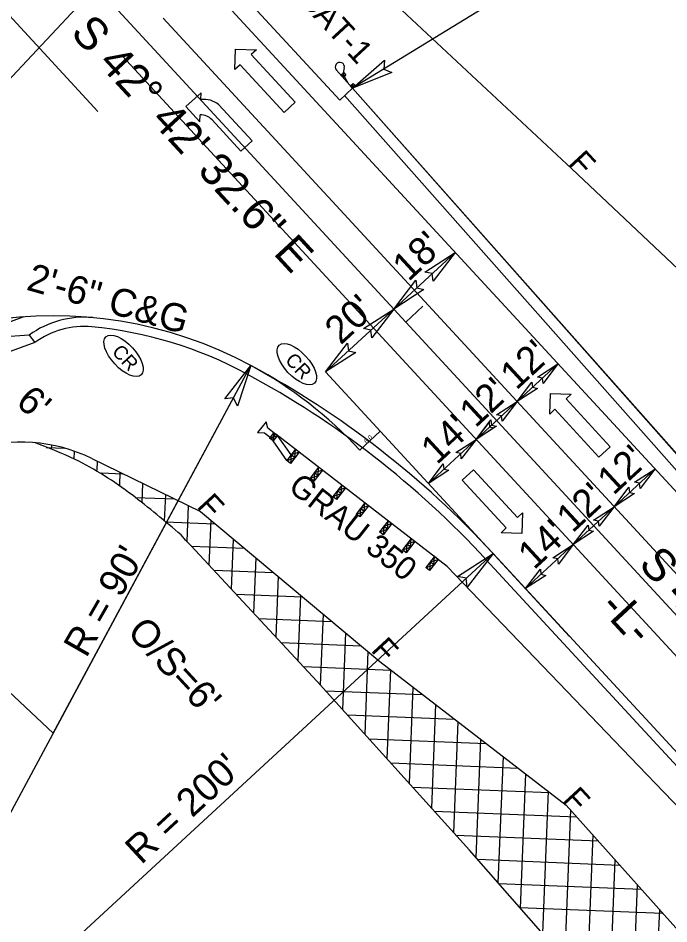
# Model space of a CAD drawing. Extents: x 1702862 to 1704514, y 793768 to 796215.
# Drawn here: x 1703316.6 to 1703456.9, y 795023.9 to 795219.2 of the extents above; entities that cross this region are included whole.
import ezdxf

# ---------------------------------------------------------------- set-up
doc = ezdxf.new("R2010")
doc.units = 0
for name, color, linetype in [('Default', 7, 'Continuous'), ('Prop Conc 2ft 6in Curb and Gutter', 7, 'Continuous'), ('Prop Conc Shoulder Berm Gutter', 7, 'Continuous'), ('Prop Dimension', 7, 'Continuous'), ('Prop Dimension Text', 7, 'Continuous'), ('Prop EOT', 7, 'Continuous'), ('Prop Guardrail', 7, 'Continuous'), ('Prop Guardrail Anchor Unit CELL', 7, 'Continuous'), ('Prop Horizontal Alignment', 7, 'Continuous'), ('Prop Horizontal Alignment Direction Label', 7, 'Continuous'), ('Prop Horizontal Alignment Tick Small', 7, 'Continuous'), ('Prop Lane Arrow CELL', 7, 'Continuous'), ('Prop Lane Lines', 7, 'Continuous'), ('Prop Leader Line Medium', 7, 'Continuous'), ('Prop Paved Shoulder', 7, 'Continuous'), ('Prop Rem of Exist Asph Pvmt', 7, 'Continuous'), ('Prop SS Fill Line', 7, 'Continuous'), ('Prop SS Misc', 7, 'Continuous'), ('Prop SS Transition Line', 7, 'Continuous'), ('Prop Structure Anchor Unit CELL', 7, 'Continuous'), ('Prop Terminator CELL', 7, 'Continuous'), ('Prop WCR CELL', 7, 'Continuous')]:
    doc.layers.add(name, color=color, linetype=linetype)

msp = doc.modelspace()

# ---------------------------------------------------------------- linework, layer by layer
at = {"layer": 'Default'}
msp.add_line((1703382.89, 795142.89), (1703435.5, 795085.89), dxfattribs=at)
at = {"layer": 'Prop Conc 2ft 6in Curb and Gutter'}
msp.add_line((1703417.51, 795102.43), (1703469.08, 795046.57), dxfattribs=at)
for centre, radius, start, end in [((1703330.77, 795134.69), 18, 84.5561, 126.0894), ((1703324.13, 795065.01), 88, 61.7203, 84.5561), ((1703272.02, 794968.13), 198, 42.7091, 61.7203)]:
    msp.add_arc(centre, radius, start, end, dxfattribs=at)
at = {"layer": 'Prop Conc Shoulder Berm Gutter'}
msp.add_line((1703388.7, 795204.04), (1703509.44, 795067.71), dxfattribs=at)
at = {"layer": 'Prop Dimension'}
for p, q in [((1703397.58, 795156.45), (1703410.81, 795168.66)), ((1703382.89, 795142.89), (1703397.58, 795156.45)), ((1703317.84, 795154.78), (1703304.2, 795149.85)), ((1703320.17, 795149.24), (1703306.25, 795144.2)), ((1703272.02, 794968.13), (1703366.77, 795144.26)), ((1703324.13, 795065.01), (1703366.77, 795144.26)), ((1703424.16, 795136.51), (1703432.98, 795144.65)), ((1703415.34, 795128.37), (1703424.16, 795136.51)), ((1703390.26, 795126.05), (1703394.67, 795130.12)), ((1703405.06, 795118.87), (1703415.34, 795128.37)), ((1703324.13, 795065.01), (1703258.57, 795126.66)), ((1703445.09, 795113.83), (1703453.91, 795121.97)), ((1703436.27, 795105.69), (1703445.09, 795113.83)), ((1703425.99, 795096.2), (1703436.27, 795105.69)), ((1703272.02, 794968.13), (1703418.98, 795103.79))]:
    msp.add_line(p, q, dxfattribs=at)
for start, end in [(136.7565, 136.7565), (42.7091, 61.7203)]:
    msp.add_arc((1703324.13, 795065.01), 90, start, end, dxfattribs=at)
at = {"layer": 'Prop EOT'}
for p, q in [((1703259.9, 795332.15), (1703737.14, 794815.13)), ((1703318.99, 795150.85), (1703320.17, 795149.24)), ((1703418.98, 795103.79), (1703636.58, 794868.05))]:
    msp.add_line(p, q, dxfattribs=at)
for centre, radius, start, end in [((1703324.13, 795065.01), 90, 61.7203, 136.7565), ((1703330.77, 795134.69), 20, 84.5561, 126.0894), ((1703272.02, 794968.13), 200, 42.7091, 61.7203)]:
    msp.add_arc(centre, radius, start, end, dxfattribs=at)
at = {"layer": 'Prop Guardrail'}
for p, q in [((1703513.1, 795063.75), (1703388.7, 795204.04)), ((1703409.13, 795100.95), (1703450.36, 795057.99)), ((1703450.36, 795057.99), (1703467.69, 795039.96))]:
    msp.add_line(p, q, dxfattribs=at)
at = {"layer": 'Prop Guardrail Anchor Unit CELL'}
for p, q in [((1703386.35, 795206.69), (1703385.21, 795207.98)), ((1703386.92, 795208.43), (1703386.7, 795207.36)), ((1703386.17, 795206.89), (1703386.78, 795207.43)), ((1703386.17, 795206.89), (1703387.24, 795206.9)), ((1703386.64, 795206.37), (1703386.17, 795206.89)), ((1703386.26, 795206.79), (1703386.35, 795206.69)), ((1703388.7, 795204.04), (1703386.35, 795206.69)), ((1703386.64, 795206.37), (1703386.78, 795207.43)), ((1703387.24, 795206.9), (1703386.64, 795206.37)), ((1703386.71, 795206.9), (1703387.67, 795205.21)), ((1703386.78, 795207.43), (1703387.24, 795206.9)), ((1703388.24, 795204.56), (1703388.84, 795205.1)), ((1703388.24, 795204.56), (1703389.3, 795204.58)), ((1703388.7, 795204.04), (1703388.24, 795204.56)), ((1703388.7, 795204.04), (1703388.84, 795205.1)), ((1703389.3, 795204.58), (1703388.7, 795204.04)), ((1703388.84, 795205.1), (1703389.3, 795204.58)), ((1703370.07, 795132.16), (1703368.23, 795129.87)), ((1703370.45, 795130.76), (1703370.07, 795132.16)), ((1703368.23, 795129.87), (1703369.69, 795129.8)), ((1703369.69, 795129.8), (1703371.29, 795128.52)), ((1703372.05, 795129.48), (1703370.45, 795130.76)), ((1703371.72, 795129.82), (1703370.81, 795128.63)), ((1703371.72, 795129.82), (1703371.6, 795128.02)), ((1703370.81, 795128.63), (1703372.52, 795129.21)), ((1703371.6, 795128.02), (1703370.81, 795128.63)), ((1703371.6, 795128.02), (1703371.2, 795128.33)), ((1703371.29, 795128.52), (1703371.67, 795129)), ((1703372.52, 795129.21), (1703371.6, 795128.02)), ((1703374.52, 795123.79), (1703371.6, 795128.02)), ((1703371.67, 795129), (1703372.05, 795129.48)), ((1703409.13, 795100.95), (1703372.12, 795129.52)), ((1703375.46, 795125), (1703372.52, 795129.21)), ((1703376.4, 795126.22), (1703374.52, 795123.79)), ((1703376.25, 795124.39), (1703376.4, 795126.22)), ((1703374.52, 795123.79), (1703376.25, 795124.39)), ((1703377.19, 795125.6), (1703375.32, 795123.18)), ((1703375.46, 795125), (1703375.32, 795123.18)), ((1703377.19, 795125.6), (1703375.46, 795125)), ((1703376.25, 795124.39), (1703375.46, 795125)), ((1703375.32, 795123.18), (1703374.52, 795123.79)), ((1703381.38, 795122.37), (1703379.55, 795119.99)), ((1703381.26, 795120.57), (1703381.38, 795122.37)), ((1703379.55, 795119.99), (1703381.26, 795120.57)), ((1703380.34, 795119.38), (1703379.55, 795119.99)), ((1703382.18, 795121.75), (1703380.34, 795119.38)), ((1703380.47, 795121.18), (1703380.34, 795119.38)), ((1703382.18, 795121.75), (1703380.47, 795121.18)), ((1703381.26, 795120.57), (1703380.47, 795121.18)), ((1703386.37, 795118.52), (1703384.46, 795116.03)), ((1703386.21, 795116.66), (1703386.37, 795118.52)), ((1703384.46, 795116.03), (1703386.21, 795116.66)), ((1703385.25, 795115.42), (1703384.46, 795116.03)), ((1703387.16, 795117.9), (1703385.25, 795115.42)), ((1703385.41, 795117.27), (1703385.25, 795115.42)), ((1703387.16, 795117.9), (1703385.41, 795117.27)), ((1703386.21, 795116.66), (1703385.41, 795117.27)), ((1703391.36, 795114.67), (1703389.51, 795112.26)), ((1703391.22, 795112.85), (1703391.36, 795114.67)), ((1703392.15, 795114.05), (1703391.36, 795114.67)), ((1703389.51, 795112.26), (1703391.22, 795112.85)), ((1703390.3, 795111.65), (1703389.51, 795112.26)), ((1703392.15, 795114.05), (1703390.3, 795111.65)), ((1703390.43, 795113.46), (1703390.3, 795111.65)), ((1703392.15, 795114.05), (1703390.43, 795113.46)), ((1703391.22, 795112.85), (1703390.43, 795113.46)), ((1703396.35, 795110.82), (1703394.49, 795108.4)), ((1703397.14, 795110.2), (1703395.28, 795107.79)), ((1703397.14, 795110.2), (1703395.42, 795109.61)), ((1703396.21, 795109), (1703396.35, 795110.82)), ((1703394.49, 795108.4), (1703396.21, 795109)), ((1703395.28, 795107.79), (1703394.49, 795108.4)), ((1703395.42, 795109.61), (1703395.28, 795107.79)), ((1703396.21, 795109), (1703395.42, 795109.61)), ((1703401.34, 795106.97), (1703399.47, 795104.55)), ((1703402.13, 795106.35), (1703400.26, 795103.94)), ((1703402.13, 795106.35), (1703400.4, 795105.76)), ((1703401.2, 795105.15), (1703401.34, 795106.97)), ((1703399.47, 795104.55), (1703401.2, 795105.15)), ((1703400.26, 795103.94), (1703399.47, 795104.55)), ((1703400.4, 795105.76), (1703400.26, 795103.94)), ((1703401.2, 795105.15), (1703400.4, 795105.76)), ((1703406.33, 795103.11), (1703404.49, 795100.74)), ((1703407.12, 795102.5), (1703405.28, 795100.13)), ((1703406.33, 795103.11), (1703405.41, 795101.93)), ((1703405.41, 795101.93), (1703407.12, 795102.5)), ((1703406.2, 795101.32), (1703406.33, 795103.11)), ((1703407.12, 795102.5), (1703406.33, 795103.11)), ((1703404.49, 795100.74), (1703406.2, 795101.32)), ((1703405.28, 795100.13), (1703404.49, 795100.74)), ((1703405.41, 795101.93), (1703405.28, 795100.13)), ((1703406.2, 795101.32), (1703405.41, 795101.93))]:
    msp.add_line(p, q, dxfattribs=at)
msp.add_ellipse((1703385.95, 795208.64), major_axis=(-0.743, -0.659), ratio=0.995379, start_param=2.210226, end_param=6.283185, dxfattribs=at)
at = {"layer": 'Prop Horizontal Alignment'}
for p, q in [((1703246.67, 795319.94), (1703723.92, 794802.92)), ((1703333.42, 795225.96), (1703157.53, 795038.5))]:
    msp.add_line(p, q, dxfattribs=at)
at = {"layer": 'Prop Horizontal Alignment Tick Small'}
msp.add_line((1703400.17, 795153.65), (1703403.84, 795157.05), dxfattribs=at)
at = {"layer": 'Prop Lane Arrow CELL'}
for p, q in [((1703363.33, 795208.07), (1703363.47, 795212.49)), ((1703363.47, 795212.49), (1703367.96, 795212.34)), ((1703367.96, 795212.34), (1703366.86, 795211.32)), ((1703366.86, 795211.32), (1703376.35, 795201.04)), ((1703364.43, 795209.09), (1703363.33, 795208.07)), ((1703373.93, 795198.8), (1703364.43, 795209.09)), ((1703356.04, 795203.09), (1703352.77, 795200.14)), ((1703355.98, 795201.61), (1703356.04, 795203.09)), ((1703352.77, 795200.14), (1703355.79, 795196.8)), ((1703367.02, 795192.75), (1703359.86, 795200.5)), ((1703376.35, 795201.04), (1703373.93, 795198.8)), ((1703355.79, 795196.8), (1703355.85, 795198.29)), ((1703358.39, 795197.23), (1703364.59, 795190.51)), ((1703364.59, 795190.51), (1703367.02, 795192.75)), ((1703431.21, 795133.82), (1703431.35, 795138.24)), ((1703431.35, 795138.24), (1703435.84, 795138.1)), ((1703435.84, 795138.1), (1703434.74, 795137.08)), ((1703434.74, 795137.08), (1703444.24, 795126.79)), ((1703432.31, 795134.84), (1703431.21, 795133.82)), ((1703441.81, 795124.55), (1703432.31, 795134.84)), ((1703444.24, 795126.79), (1703441.81, 795124.55)), ((1703412.35, 795119.55), (1703414.77, 795121.78)), ((1703414.77, 795121.78), (1703424.27, 795111.5)), ((1703421.85, 795109.26), (1703412.35, 795119.55)), ((1703424.27, 795111.5), (1703425.37, 795112.51)), ((1703425.37, 795112.51), (1703425.23, 795108.1)), ((1703420.74, 795108.24), (1703421.85, 795109.26)), ((1703425.23, 795108.1), (1703420.74, 795108.24))]:
    msp.add_line(p, q, dxfattribs=at)
for centre, radius, start, end in [((1703356.6, 795196.41), 5.25, 51.3851, 96.6968), ((1703355.99, 795195.03), 3.27, 42.7091, 92.3672)]:
    msp.add_arc(centre, radius, start, end, dxfattribs=at)
at = {"layer": 'Prop Lane Lines'}
for p, q in [((1703233.45, 795307.73), (1703333.8, 795199.01)), ((1703347.89, 795219.14), (1703550.56, 794999.58)), ((1703339.07, 795211), (1703542.22, 794990.92))]:
    msp.add_line(p, q, dxfattribs=at)
at = {"layer": 'Prop Leader Line Medium'}
msp.add_line((1703492.5, 795267.75), (1703388.7, 795204.04), dxfattribs=at)
at = {"layer": 'Prop Paved Shoulder'}
for p, q in [((1703262.84, 795334.86), (1703385.95, 795201.5)), ((1703385.95, 795201.5), (1703388.7, 795204.04)), ((1703386.98, 795202.46), (1703507.31, 795066.6))]:
    msp.add_line(p, q, dxfattribs=at)
msp.add_arc((1703324.13, 795065.01), 86, 93.4265, 136.7565, dxfattribs=at)
at = {"layer": 'Prop Rem of Exist Asph Pvmt'}
for p, q in [((1703322.61, 795126.63), (1703326.65, 795126.47)), ((1703323.75, 795127.16), (1703323.71, 795126.17)), ((1703328.7, 795125.82), (1703328.63, 795124.13)), ((1703333.62, 795123.68), (1703333.54, 795121.71)), ((1703334.48, 795121.15), (1703339.17, 795120.96)), ((1703338.53, 795121.28), (1703338.41, 795118.51)), ((1703343.43, 795118.88), (1703343.27, 795114.67)), ((1703348.34, 795116.47), (1703348.11, 795110.71)), ((1703341.81, 795115.85), (1703350.31, 795115.51)), ((1703353.25, 795114.07), (1703352.94, 795106.37)), ((1703348.26, 795110.59), (1703359.03, 795110.16)), ((1703358.13, 795110.91), (1703357.74, 795101.25)), ((1703352.67, 795106.65), (1703351.72, 795107.76)), ((1703352.67, 795106.65), (1703353.81, 795105.47)), ((1703362.97, 795106.87), (1703362.54, 795096.09)), ((1703353.91, 795105.36), (1703365.32, 795104.9)), ((1703367.81, 795102.82), (1703367.34, 795090.94)), ((1703358.75, 795100.16), (1703371.62, 795099.65)), ((1703372.65, 795098.78), (1703372.13, 795085.79)), ((1703363.59, 795094.96), (1703377.91, 795094.39)), ((1703377.5, 795094.74), (1703376.93, 795080.64)), ((1703382.34, 795090.69), (1703381.73, 795075.46)), ((1703368.43, 795089.77), (1703384.21, 795089.13)), ((1703387.18, 795086.65), (1703386.52, 795070.15)), ((1703373.27, 795084.57), (1703390.5, 795083.88)), ((1703392.02, 795082.61), (1703391.31, 795064.84)), ((1703378.11, 795079.37), (1703396.99, 795078.62)), ((1703396.87, 795078.71), (1703396.1, 795059.53)), ((1703382.89, 795074.18), (1703403.84, 795073.34)), ((1703401.72, 795074.97), (1703400.89, 795054.22)), ((1703406.58, 795071.23), (1703405.69, 795048.91)), ((1703387.57, 795068.98), (1703410.69, 795068.06)), ((1703411.43, 795067.48), (1703410.48, 795043.6)), ((1703392.26, 795063.79), (1703417.54, 795062.78)), ((1703416.29, 795063.74), (1703415.27, 795038.25)), ((1703421.14, 795060), (1703420.05, 795032.8)), ((1703396.94, 795058.6), (1703424.39, 795057.5)), ((1703426, 795056.26), (1703424.84, 795027.34)), ((1703401.63, 795053.41), (1703431.24, 795052.23)), ((1703430.85, 795052.52), (1703429.63, 795021.89)), ((1703406.31, 795048.22), (1703437.01, 795046.99)), ((1703435.69, 795048.47), (1703434.41, 795016.44)), ((1703410.99, 795043.03), (1703441.64, 795041.8)), ((1703440.48, 795043.1), (1703439.2, 795010.99)), ((1703415.63, 795037.84), (1703446.27, 795036.61)), ((1703445.27, 795037.73), (1703443.98, 795005.35)), ((1703420.18, 795032.65), (1703450.9, 795031.42)), ((1703450.06, 795032.37), (1703448.82, 795001.4)), ((1703424.73, 795027.47), (1703455.53, 795026.23)), ((1703454.85, 795027), (1703453.93, 795004.05))]:
    msp.add_line(p, q, dxfattribs=at)
msp.add_lwpolyline([(1703446.88, 795000.39), (1703443.63, 795005.93), (1703413.93, 795039.78), (1703381.07, 795076.19), (1703353.81, 795105.47)], dxfattribs=at)
msp.add_spline([(1703351.72, 795107.76), (1703341.14, 795116.4), (1703328.87, 795124.03), (1703320.09, 795127.66)], degree=3, dxfattribs=at)
at = {"layer": 'Prop SS Fill Line'}
for p, q in [((1703399.32, 795220.91), (1703435.98, 795186.71)), ((1703435.98, 795186.71), (1703472.38, 795152.27)), ((1703332.5, 795124.23), (1703355.89, 795112.78)), ((1703355.89, 795112.78), (1703394.59, 795080.46)), ((1703394.59, 795080.46), (1703434.77, 795049.5)), ((1703434.77, 795049.5), (1703468.06, 795012.19))]:
    msp.add_line(p, q, dxfattribs=at)
at = {"layer": 'Prop SS Transition Line'}
msp.add_arc((1703317.11, 795092.79), 35, 63.9216, 107.5505, dxfattribs=at)
at = {"layer": 'Prop Terminator CELL'}
for points in [[(1703397.18, 795207.43), (1703388.7, 795204.04), (1703395.58, 795210.14), (1703395.43, 795208.17)], [(1703404.3, 795164.44), (1703410.81, 795168.66), (1703406.08, 795162.45), (1703405.88, 795164.11)], [(1703404.1, 795160.67), (1703397.58, 795156.45), (1703402.31, 795162.67), (1703402.52, 795161.01)], [(1703391.07, 795152.23), (1703397.58, 795156.45), (1703392.85, 795150.24), (1703392.65, 795151.9)], [(1703389.4, 795147.11), (1703382.89, 795142.89), (1703387.62, 795149.1), (1703387.82, 795147.44)], [(1703361.14, 795137.07), (1703366.77, 795144.26), (1703363.89, 795135.54), (1703363.03, 795137.31)], [(1703428.57, 795141.79), (1703432.98, 795144.65), (1703429.78, 795140.44), (1703429.64, 795141.57)], [(1703428.57, 795139.36), (1703424.16, 795136.51), (1703427.36, 795140.71), (1703427.5, 795139.59)], [(1703419.75, 795133.65), (1703424.16, 795136.51), (1703420.96, 795132.3), (1703420.82, 795133.43)], [(1703419.75, 795131.22), (1703415.34, 795128.37), (1703418.54, 795132.57), (1703418.68, 795131.45)], [(1703419.18, 795130.85), (1703415.34, 795128.37), (1703418.13, 795132.03), (1703418.25, 795131.05)], [(1703410.94, 795125.51), (1703415.34, 795128.37), (1703412.14, 795124.16), (1703412.01, 795125.29)], [(1703409.46, 795121.73), (1703405.06, 795118.87), (1703408.26, 795123.08), (1703408.39, 795121.95)], [(1703449.5, 795119.12), (1703453.91, 795121.97), (1703450.71, 795117.77), (1703450.57, 795118.89)], [(1703449.5, 795116.69), (1703445.09, 795113.83), (1703448.29, 795118.04), (1703448.43, 795116.91)], [(1703440.68, 795110.98), (1703445.09, 795113.83), (1703441.89, 795109.63), (1703441.75, 795110.75)], [(1703440.68, 795108.55), (1703436.27, 795105.69), (1703439.47, 795109.9), (1703439.61, 795108.78)], [(1703431.87, 795102.84), (1703436.27, 795105.69), (1703433.07, 795101.49), (1703432.93, 795102.61)], [(1703411.31, 795098.82), (1703418.98, 795103.79), (1703413.41, 795096.48), (1703413.17, 795098.43)], [(1703430.39, 795099.05), (1703425.99, 795096.2), (1703429.19, 795100.4), (1703429.32, 795099.28)]]:
    msp.add_lwpolyline(points, close=True, dxfattribs=at)
at = {"layer": 'Prop WCR CELL'}
for centre in [(1703339.32, 795146.37), (1703376.68, 795144.57)]:
    msp.add_ellipse(centre, major_axis=(3.8, -4.12), ratio=0.462467, dxfattribs=at)

# ---------------------------------------------------------------- texts
at = {"layer": 'Prop Dimension'}
for s, rotation, p in [("6'", 319.674, (1703315.83, 795135.94)), ("O/S=6'", 312.7091, (1703339.86, 795086.65))]:
    msp.add_text(s, height=6, rotation=rotation, dxfattribs=at).set_placement(p)
at = {"layer": 'Prop Dimension Text'}
for s, height, rotation, p in [("18'", 6, 42.7091, (1703400.76, 795162.23)), ('2\'-6" C&G', 6, 344.2431, (1703318.13, 795160.67)), ("20'", 6, 42.7091, (1703386.16, 795148.58)), ("12'", 6, 42.7091, (1703424, 795138.81)), ("12'", 6, 42.7091, (1703415.2, 795130.69)), ("14'", 6, 42.7091, (1703406.89, 795122.75)), ('6.0', 1, 42.7091, (1703391.7, 795127.37)), ("12'", 6, 42.7091, (1703444.93, 795116.14)), ("12'", 6, 42.7091, (1703436.13, 795108.02)), ("14'", 6, 42.7091, (1703427.82, 795100.08)), ("R = 90'", 6, 60.1006, (1703331.27, 795081.07)), ("R = 200'", 6, 42.7091, (1703343.13, 795036.53))]:
    msp.add_text(s, height=height, rotation=rotation, dxfattribs=at).set_placement(p)
at = {"layer": 'Prop Guardrail Anchor Unit CELL'}
msp.add_text('CAT-1', height=5, rotation=312.7301, dxfattribs=at).set_placement((1703376.71, 795223.13))
at = {"layer": 'Prop Horizontal Alignment Direction Label'}
for s, p in [('S 42%%d 42\' 32.6" E', (1703327.66, 795215.83)), ('S 42%%d 42\' 32.6" E', (1703450.14, 795101.27)), ('-L-', (1703441.69, 795091.97))]:
    msp.add_text(s, height=7, rotation=312.7091, dxfattribs=at).set_placement(p)
at = {"layer": 'Prop SS Misc'}
for p in [(1703435.02, 795187.76), (1703354.93, 795113.82), (1703392.47, 795082.8), (1703433.81, 795050.54)]:
    msp.add_text('F', height=5, rotation=312.7091, dxfattribs=at).set_placement(p)
at = {"layer": 'Prop Structure Anchor Unit CELL'}
msp.add_text('GRAU 350', height=5, rotation=321.8351, dxfattribs=at).set_placement((1703374.57, 795117.54))
at = {"layer": 'Prop WCR CELL'}
for p in [(1703336.64, 795147.1), (1703373.99, 795145.3)]:
    msp.add_text('CR', height=3, rotation=312.7091, dxfattribs=at).set_placement(p)

doc.saveas('drawing.dxf')
